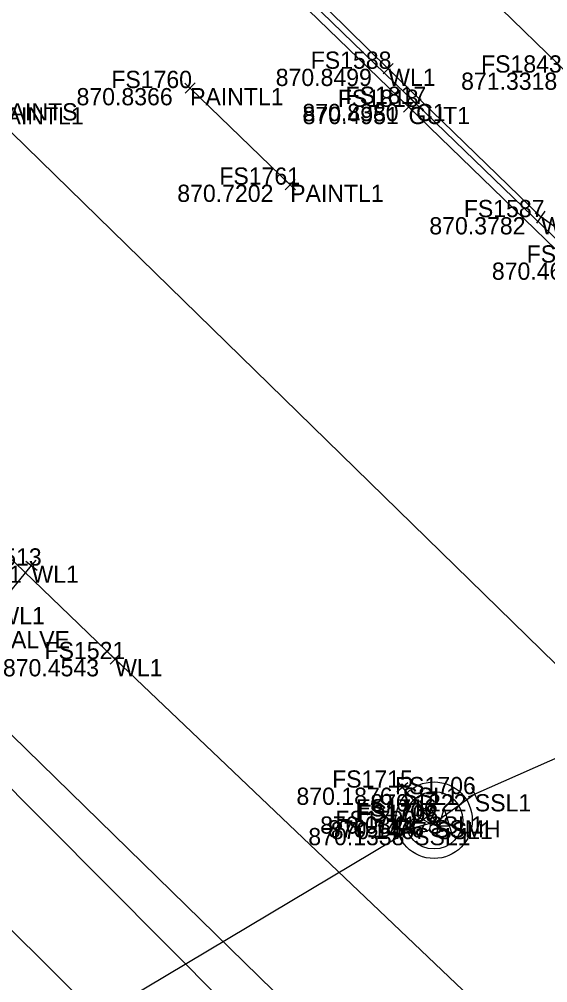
# Model space of a CAD drawing. Extents: x 1469677 to 1493262, y 375219 to 389293.
# Drawn here: x 1479592.9 to 1479629.7, y 379910.3 to 379977.4 of the extents above; entities that cross this region are included whole.
import ezdxf

# ---------------------------------------------------------------- set-up
doc = ezdxf.new("R2010")
doc.units = 0
for name, color, linetype in [('Building', 7, 'Continuous'), ('DR_X_Drive_Pipe', 7, 'Continuous'), ('DV_X_Text', 7, 'Continuous'), ('GK_Visualization', 7, 'Continuous'), ('PNTELEV', 7, 'Continuous'), ('RD_P_Text', 7, 'Continuous'), ('RW_P_Esmt_SW', 7, 'Continuous'), ('RW_X_CL_20', 7, 'Continuous'), ('RW_X_Esmt_General', 7, 'Continuous'), ('SV_X_Mon_Cells_Found', 7, 'Continuous'), ('SV_X_Text_Elevation', 7, 'Continuous'), ('UT_X_Electric', 7, 'Continuous')]:
    doc.layers.add(name, color=color, linetype=linetype)

msp = doc.modelspace()

# ---------------------------------------------------------------- linework, layer by layer
at = {"layer": 'Building'}
for points in [[(1479604.82, 379972.583), (1479611.787, 379965.856)], [(1479636.371, 379879.555), (1479574.01, 379942.241)], [(1479627.792, 379878.685), (1479575.124, 379931.128)]]:
    msp.add_lwpolyline(points, dxfattribs=at)
at = {"layer": 'DR_X_Drive_Pipe'}
for points in [[(1479473.217, 380054.881), (1479498.741, 380029.974), (1479514.505, 380014.087), (1479533.448, 379996.736), (1479556.003, 379974.32), (1479574.861, 379956.271), (1479584.403, 379947.432), (1479599.597, 379932.82), (1479630.106, 379903.783), (1479644.769, 379889.723), (1479654.209, 379882.356), (1479664.266, 379872.629), (1479692.509, 379845.847), (1479712.672, 379826.686), (1479730.739, 379809.851), (1479753.15, 379788.309), (1479771.842, 379770.542), (1479781.678, 379761.101)], [(1479688.353, 379908.314), (1479682.752, 379913.809), (1479675.346, 379920.323), (1479659.938, 379935.366), (1479654.757, 379940.471), (1479653.168, 379946.481), (1479650.478, 379950.403), (1479643.418, 379958.357), (1479641.035, 379960.303), (1479633.713, 379960.434), (1479629.263, 379963.594), (1479618.613, 379973.926), (1479604.754, 379987.567), (1479586.915, 380004.501)], [(1479451.52, 379837.183), (1479469.615, 379848.276), (1479481.983, 379856.403), (1479496.242, 379865.929), (1479520, 379881.306), (1479538.557, 379892.999), (1479553.442, 379903.409), (1479554.944, 379904.326), (1479564.844, 379911.311), (1479573.24, 379917.005), (1479582.403, 379926.468), (1479585.515, 379929.786), (1479589.646, 379934.736), (1479591.405, 379936.451), (1479593.775, 379939.335)]]:
    msp.add_lwpolyline(points, dxfattribs=at)
at = {"layer": 'PNTELEV'}
for p, q in [((1479618.972, 379973.578), (1479618.254, 379974.274)), ((1479618.265, 379973.567), (1479618.961, 379974.285)), ((1479618.613, 379973.926), (1479618.613, 379973.926)), ((1479604.46, 379972.931), (1479605.18, 379972.236)), ((1479605.167, 379972.943), (1479604.473, 379972.224)), ((1479604.82, 379972.583), (1479604.82, 379972.583)), ((1479620.388, 379970.926), (1479619.67, 379971.622)), ((1479619.681, 379970.915), (1479620.377, 379971.633)), ((1479620.917, 379971.135), (1479620.197, 379971.83)), ((1479620.21, 379971.123), (1479620.904, 379971.842)), ((1479620.029, 379971.274), (1479620.029, 379971.274)), ((1479620.557, 379971.482), (1479620.557, 379971.482)), ((1479612.134, 379966.215), (1479611.44, 379965.496)), ((1479611.427, 379966.203), (1479612.147, 379965.508)), ((1479611.787, 379965.856), (1479611.787, 379965.856)), ((1479629.671, 379963.304), (1479628.855, 379963.883)), ((1479628.974, 379963.186), (1479629.552, 379964.001)), ((1479629.263, 379963.594), (1479629.263, 379963.594)), ((1479593.389, 379939.652), (1479594.161, 379939.017)), ((1479593.458, 379938.948), (1479594.092, 379939.721)), ((1479593.775, 379939.335), (1479593.775, 379939.335)), ((1479599.237, 379933.166), (1479599.957, 379932.473)), ((1479599.944, 379933.18), (1479599.25, 379932.459)), ((1479599.597, 379932.82), (1479599.597, 379932.82)), ((1479619.981, 379924.201), (1479619.225, 379923.547)), ((1479619.276, 379924.252), (1479619.93, 379923.496)), ((1479619.603, 379923.874), (1479619.603, 379923.874)), ((1479625.104, 379923.619), (1479624.19, 379923.215)), ((1479624.849, 379922.959), (1479624.445, 379923.874)), ((1479624.647, 379923.417), (1479624.647, 379923.417)), ((1479621.719, 379922.194), (1479620.963, 379921.539)), ((1479621.014, 379922.245), (1479621.668, 379921.488)), ((1479620.553, 379920.581), (1479620.289, 379921.545)), ((1479621.341, 379921.867), (1479621.341, 379921.867)), ((1479622.369, 379921.777), (1479621.557, 379921.193)), ((1479622.255, 379921.079), (1479621.671, 379921.891)), ((1479621.963, 379921.485), (1479621.963, 379921.485)), ((1479620.903, 379921.195), (1479619.939, 379920.931)), ((1479620.421, 379921.063), (1479620.421, 379921.063))]:
    msp.add_line(p, q, dxfattribs=at)
at = {"layer": 'RD_P_Text'}
for points in [[(1479773.254, 379993.873), (1479762.766, 379988.772), (1479738.122, 379976.644), (1479720.845, 379968.214), (1479698.694, 379957.239), (1479678.815, 379947.539), (1479674.951, 379945.56), (1479671.194, 379943.855), (1479668.836, 379942.929), (1479666.481, 379942.243), (1479664.295, 379941.704), (1479662.026, 379941.397), (1479659.994, 379941.512), (1479654.023, 379942.767), (1479648.758, 379945.101), (1479643.81, 379948.553), (1479642.638, 379949.517), (1479640.65, 379951.389), (1479638.379, 379953.495), (1479620.029, 379971.274), (1479601.931, 379988.801), (1479602.178, 379989.373), (1479582.142, 380008.015)], [(1479772.982, 379994.381), (1479762.438, 379989.23), (1479737.891, 379977.225), (1479720.638, 379968.612), (1479698.71, 379957.883), (1479678.409, 379947.915), (1479674.816, 379946.157), (1479670.835, 379944.353), (1479668.74, 379943.532), (1479666.343, 379942.649), (1479664.179, 379942.195), (1479661.876, 379941.901), (1479659.999, 379941.972), (1479653.935, 379943.268), (1479649.182, 379945.527), (1479644.261, 379948.889), (1479643.432, 379949.993), (1479639.011, 379953.958), (1479638.818, 379953.848), (1479620.557, 379971.482), (1479582.44, 380008.391)]]:
    msp.add_lwpolyline(points, dxfattribs=at)
at = {"layer": 'RW_X_CL_20'}
for p, q in [((1479621.804, 379923.604), (1479621.804, 379923.604)), ((1479621.804, 379921.604), (1479621.804, 379921.604)), ((1479621.804, 379921.604), (1479621.804, 379921.604)), ((1479621.804, 379921.604), (1479621.804, 379921.604)), ((1479621.804, 379919.604), (1479621.804, 379919.604))]:
    msp.add_line(p, q, dxfattribs=at)
msp.add_circle((1479621.804, 379921.604), 2, dxfattribs=at)
at = {"layer": 'RW_X_Esmt_General'}
for points in [[(1479621.471, 379922.29), (1479621.446, 379922.315), (1479621.408, 379922.34), (1479621.295, 379922.378), (1479621.156, 379922.404), (1479621.056, 379922.404), (1479621.018, 379922.404), (1479620.854, 379922.366), (1479620.716, 379922.29), (1479620.627, 379922.189), (1479620.602, 379922.088), (1479620.602, 379922.013), (1479620.627, 379921.912), (1479620.728, 379921.824), (1479621.421, 379921.446), (1479621.484, 379921.396), (1479621.509, 379921.345), (1479621.534, 379921.27), (1479621.534, 379921.194), (1479621.522, 379921.119), (1479621.509, 379921.068), (1479621.484, 379921.005), (1479621.459, 379920.955), (1479621.434, 379920.917), (1479621.396, 379920.879), (1479621.358, 379920.854), (1479621.308, 379920.829), (1479621.27, 379920.816), (1479621.156, 379920.804), (1479620.98, 379920.804), (1479620.867, 379920.829), (1479620.703, 379920.917), (1479620.602, 379920.993)], [(1479622.013, 379920.804), (1479622.517, 379922.404), (1479623.008, 379920.804)], [(1479622.882, 379921.181), (1479622.139, 379921.181)]]:
    msp.add_lwpolyline(points, dxfattribs=at)
for radius in [2.667, 2]:
    msp.add_circle((1479621.804, 379921.604), radius, dxfattribs=at)
at = {"layer": 'SV_X_Mon_Cells_Found'}
for points in [[(1477206.544, 382340.781), (1479657.335, 379947.979), (1480466.338, 379191.878)], [(1477164.629, 382297.849), (1479615.888, 379904.59), (1480413.414, 379159.216)]]:
    msp.add_lwpolyline(points, dxfattribs=at)
at = {"layer": 'SV_X_Text_Elevation'}
msp.add_line((1478152.942, 381374.848), (1479636.611, 379926.284), dxfattribs=at)
at = {"layer": 'UT_X_Electric'}
for points in [[(1479823.042, 380000.22), (1479820.4, 379999.933), (1479798.147, 379991.168), (1479736.037, 379968.233), (1479710.112, 379956.448), (1479679.103, 379944.837), (1479664.157, 379939.675), (1479652.585, 379935.616), (1479645.234, 379932.512), (1479624.647, 379923.417), (1479621.963, 379921.485), (1479620.421, 379921.063), (1479600.276, 379909.045), (1479588.442, 379902.577), (1479565.169, 379891.726), (1479542.109, 379880.195), (1479514.622, 379866.871)], [(1479619.603, 379923.874), (1479621.341, 379921.867)]]:
    msp.add_lwpolyline(points, dxfattribs=at)

# ---------------------------------------------------------------- texts
at = {"layer": 'DV_X_Text'}
for s, p in [('870.8499', (1479610.78, 379972.726)), ('871.3318', (1479623.691, 379972.46)), ('870.8366', (1479596.912, 379971.383)), ('870.8380', (1479612.639, 379970.282)), ('870.4951', (1479612.657, 379970.074)), ('870.7202', (1479603.926, 379964.656)), ('870.3782', (1479621.478, 379962.394)), ('870.4676', (1479625.833, 379959.234)), ('870.5431', (1479586.403, 379938.135)), ('870.4543', (1479591.784, 379931.62)), ('870.1876', (1479612.225, 379922.674)), ('870.1222', (1479617.372, 379922.217)), ('870.0841', (1479613.875, 379920.667)), ('870.1476', (1479614.416, 379920.404)), ('870.1467', (1479614.613, 379920.285)), ('870.1338', (1479613.052, 379919.863))]:
    msp.add_text(s, height=1.2, dxfattribs=at).set_placement(p)
at = {"layer": 'GK_Visualization'}
for s, p in [('WL1', (1479618.613, 379972.726)), ('PAINTL1', (1479604.82, 379971.383)), ('PAINTL1', (1479590.899, 379970.051)), ('PAINTS', (1479591.184, 379970.329)), ('GUT1', (1479620.029, 379970.074)), ('C1', (1479620.557, 379970.282)), ('PAINTL1', (1479611.787, 379964.656)), ('WL1', (1479629.263, 379962.394)), ('WL1', (1479593.775, 379938.135)), ('WL1', (1479591.405, 379935.251)), ('WVALVE', (1479589.762, 379933.572)), ('WL1', (1479599.597, 379931.62)), ('SSL1', (1479619.603, 379922.674)), ('SSL1', (1479624.647, 379922.217)), ('SSL1', (1479621.341, 379920.667)), ('SSMH', (1479621.804, 379920.404)), ('SSL1', (1479621.963, 379920.285)), ('SSL1', (1479620.421, 379919.863))]:
    msp.add_text(s, height=1.2, dxfattribs=at).set_placement(p)
at = {"layer": 'RW_P_Esmt_SW'}
for s, p in [('FS1588', (1479613.219, 379973.926)), ('FS1843', (1479625.08, 379973.66)), ('FS1760', (1479599.331, 379972.583)), ('FS1818', (1479615.108, 379971.274)), ('FS1817', (1479615.645, 379971.482)), ('FS1761', (1479606.853, 379965.856)), ('FS1587', (1479623.878, 379963.594)), ('FS1586', (1479628.253, 379960.434)), ('FS1513', (1479588.863, 379939.335)), ('FS1521', (1479594.682, 379932.82)), ('FS1715', (1479614.71, 379923.874)), ('FS1706', (1479619.092, 379923.417)), ('FS1707', (1479616.325, 379921.604)), ('FS1716', (1479616.373, 379921.867)), ('FS1708', (1479616.474, 379921.485)), ('FS1709', (1479614.932, 379921.063))]:
    msp.add_text(s, height=1.2, dxfattribs=at).set_placement(p)

doc.saveas('drawing.dxf')
